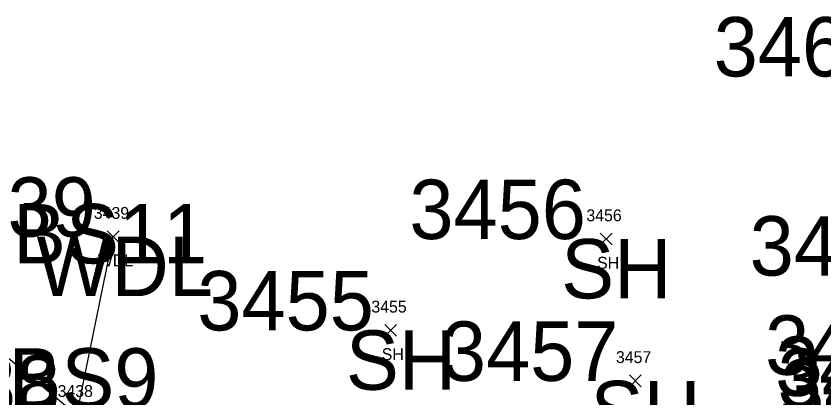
# Model space of a CAD drawing. Extents: x 1616840 to 1618410, y 488554 to 491945.
# Drawn here: x 1617625.1 to 1617761.2, y 491880.3 to 491944.6 of the extents above; entities that cross this region are included whole.
import ezdxf

# ---------------------------------------------------------------- set-up
doc = ezdxf.new("R2010")
doc.units = 0
for name, color, linetype in [('C_A', 7, 'Continuous'), ('C_I', 7, 'Continuous'), ('L_A', 7, 'Continuous'), ('L_I', 7, 'Continuous'), ('L_TIC', 7, 'Continuous'), ('LAWA', 7, 'Continuous')]:
    doc.layers.add(name, color=color, linetype=linetype)

msp = doc.modelspace()

# ---------------------------------------------------------------- linework, layer by layer
at = {"layer": 'L_TIC'}
for points in [[(1617640.44, 491906.48), (1617642.44, 491908.48)], [(1617642.44, 491906.48), (1617640.44, 491908.48)], [(1617723.52, 491906.08), (1617725.52, 491908.08)], [(1617725.52, 491906.08), (1617723.52, 491908.08)], [(1617687.22, 491890.7), (1617689.22, 491892.7)], [(1617689.22, 491890.7), (1617687.22, 491892.7)], [(1617728.44, 491882.2), (1617730.44, 491884.2)], [(1617730.44, 491882.2), (1617728.44, 491884.2)]]:
    msp.add_lwpolyline(points, dxfattribs=at)
at = {"layer": 'LAWA'}
msp.add_lwpolyline([(1617614.98, 491912.98), (1617621.74, 491888.69), (1617635.33, 491877.49), (1617641.44, 491907.48)], dxfattribs=at)
msp.add_lwpolyline([(1617614.98, 491912.98), (1617621.74, 491888.69), (1617635.33, 491877.49), (1617641.44, 491907.48)], dxfattribs=at)

# ---------------------------------------------------------------- texts
at = {"layer": 'C_A'}
for s, p in [('WDL ST BS11', (1617570.33, 491902.98)), ('WDL', (1617628.53, 491897.48)), ('SH', (1617716.96, 491897.08)), ('SH', (1617680.67, 491881.7)), ('WDL BS9', (1617590.36, 491878.69)), ('SH', (1617721.89, 491873.2))]:
    msp.add_text(s, height=10, dxfattribs=at).set_placement(p)
at = {"layer": 'C_I'}
for s, p in [('3468', (1617742.66, 491934.46)), ('3439', (1617608.77, 491907.48)), ('3456', (1617691.37, 491907.08)), ('3467', (1617748.73, 491900.93)), ('3455', (1617655.63, 491891.7)), ('3457', (1617696.85, 491883.2)), ('3466', (1617751.34, 491884.23)), ('3465', (1617753.02, 491880.66)), ('3464', (1617753.43, 491878.65)), ('3438', (1617602.74, 491877.49)), ('3463', (1617753.86, 491876.78))]:
    msp.add_text(s, height=10, dxfattribs=at).set_placement(p)
at = {"layer": 'L_A'}
for s, p in [('WDL', (1617638.86, 491902.48)), ('SH', (1617723.01, 491902.08)), ('SH', (1617686.71, 491886.7))]:
    msp.add_text(s, height=2, dxfattribs=at).set_placement(p)
at = {"layer": 'L_I'}
for s, p in [('3439', (1617638.18, 491910.48)), ('3456', (1617721.2, 491910.08)), ('3455', (1617684.96, 491894.7)), ('3457', (1617726.18, 491886.2)), ('3438', (1617632.07, 491880.49)), ('3438', (1617632.07, 491880.49))]:
    msp.add_text(s, height=2, dxfattribs=at).set_placement(p)

doc.saveas('drawing.dxf')
